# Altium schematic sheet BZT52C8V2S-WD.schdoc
size 127 x 101 mm
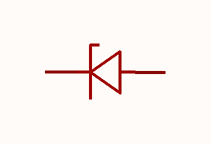
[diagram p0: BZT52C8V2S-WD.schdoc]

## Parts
D?  bzt52c8v2s_c523832  [SOD-323_L1.6-W1.3-LS2.7-RD]  (value not drawn)

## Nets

Not connected (* = marked no-connect by the designer): D? 1(K) 2(A)

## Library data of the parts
D? = bzt52c8v2s_c523832: 二极管配置:1个独立式;稳压值(标称值):8.2V;稳压值(范围值):7.7V~8.7V;耗散功率(Pd):200mW;; Manufacturer: MDD(辰达半导体); Symbol: BZT52C8V2S-WD; AddInBom: yes; ModelId: 39bca86493a8419684ee2090e9340edf; ModelTransform: 104.3305,51.181,0,0,0,0,0,0,0; Diode Configuration: 1个独立式; Zener Voltage(Nom): 8.2V; Reverse Leakage Current (Ir): 500nA@5V; Pd - Power Dissipation: 200mW; Impedance(Zzt): 30Ω; Tolerance: ±5%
